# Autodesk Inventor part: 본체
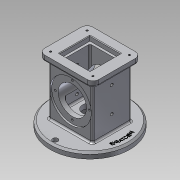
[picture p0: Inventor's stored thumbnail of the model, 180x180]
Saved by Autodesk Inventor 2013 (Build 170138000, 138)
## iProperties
Created: 2019-08
Part Number: 본체
Material: 알루미늄 6061
Document SubType Name: Modeling
Designer: default
Density: 2.71 g/cm^3
Mass: 1041.14 g
Surface Area: 787.451 cm^2
Volume: 384.186 cm^3
Author: default
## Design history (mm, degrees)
sketch "스케치1"
  geometry: C1 r 67.5 at (0, 0); 1 further point
  constraints: 1 centre point, 1 coincident
  dimensions: "d0" = 135 diameter of C1
extrude "돌출1" new body sketch "스케치1" distance "d2" = 10; taper "d3" = 0 deg
chamfer "모따기1" distance "d4" = 3; stored, may be unused: second distance "d5" = 2, angle "d6" = 45 deg
sketch "스케치2"
  geometry: L1 (-37, 33)-(37, 33); L2 (37, 33)-(37, -33); L3 (37, -33)-(-37, -33); L4 (-37, -33)-(-37, 33); L5 (-37, 33)-(37, -33); L6 (37, 33)-(-37, -33); C1 r 64.5 at (0, 0) reference
  constraints: 12 end point, 2 midpoint, 2 parallel, 1 horizontal, 1 perpendicular
  dimensions: "d7" = 74 distance of L1.start L1.end; "d9" = 66 distance of L1.end L2.end
extrude "돌출2" join sketch "스케치2" distance "d10" = 98; taper "d11" = 0 deg
sketch "스케치3"
  geometry: L1 (37, 33)-(-37, 33) reference; L2 (-37, 33)-(-37, -33) reference; L3 (-37, -33)-(37, -33) reference; L4 (37, -33)-(37, 33) reference; L5 (-46, 41)-(46, 41); L6 (46, 41)-(46, -41); L7 (46, -41)-(-46, -41); L8 (-46, -41)-(-46, 41); L9 (-46, 41)-(46, -41); L10 (46, 41)-(-46, -41); 1 further point
  constraints: 12 end point, 2 midpoint, 2 parallel, 1 horizontal, 1 perpendicular
  dimensions: "d12" = 92 distance of L5.start L5.end; "d14" = 82 distance of L5.end L6.end
extrude "돌출3" join sketch "스케치3" distance "d15" = 10; taper "d16" = 0 deg
fillet "모깎기1" dims "d17" = 10
fillet "모깎기2" dims "d18" = 3
fillet "모깎기3" dims "d19" = 3
fillet "모깎기4" dims "d20" = 3
sketch "스케치4"
  geometry: L1 (34, 36)-(-34, 36) reference; C1 r 64.5 at (0, 0) reference; 2 further points
  constraints: 2 vertical alignment, 1 midpoint
  dimensions: "d21" = 59 distance of C1.centre point (0, 59)
hole "구멍1" sketch "스케치4" at (0, 59) diameter "d22" = 9; stored, may be unused: countersink angle "d26" = 90 deg, drill point angle "d28" = 118 deg; dims "d23" = 6, "d24" = 4, "d25" = 2, "d27" = 8
sketch "스케치5"
  geometry: L1 (-26, 26)-(26, 26); L2 (26, 26)-(26, -26); L3 (26, -26)-(-26, -26); L4 (-26, -26)-(-26, 26); L5 (-26, 26)-(26, -26); L6 (26, 26)-(-26, -26); 1 further point
  constraints: 12 end point, 2 midpoint, 2 parallel, 2 perpendicular, 1 horizontal
  dimensions: "d32" = 52 distance of L1.start L1.end
extrude "돌출4" cut sketch "스케치5" distance "d34" = 8; taper "d35" = 0 deg
sketch "스케치7"
  geometry: L1 (-19, 22)-(19, 22); L2 (22, 19)-(22, -19); L3 (19, -22)-(-19, -22); L4 (-22, -19)-(-22, 19); L5 (-22, 22)-(22, -22); L6 (22, 22)-(-22, -22); A1 r 3 centre (-19, 19) between (-19, 22) and (-22, 19); A2 r 3 centre (19, 19) between (22, 19) and (19, 22); A3 r 3 centre (19, -19) between (19, -22) and (22, -19); A4 r 3 centre (-19, -19) between (-22, -19) and (-19, -22); 1 further point
  constraints: 12 end point, 8 point on circle, 8 point on line, 8 tangent, 4 centre point, 3 equal radius, 2 midpoint, 2 parallel, 2 perpendicular, 1 horizontal
  dimensions: "d36" = 44 distance of L5.start L6.start; "d38" = 3 radius of A1
extrude "돌출5" cut sketch "스케치7" distance "d39" = 74; taper "d40" = 0 deg
sketch "스케치8"
  geometry: L1 (63.5, 0)-(63.5, 10) reference; L2 (63.5, 10)-(64.5, 10) reference; L3 (64.5, 10)-(67.5, 7) reference; L4 (67.5, 7)-(67.5, 0) reference; L5 (67.5, 0)-(63.5, 0) reference; L6 (-37, 13)-(-37, 95) reference; L7 (-40, 98)-(-46, 98) reference; L8 (-46, 98)-(-46, 108) reference; L9 (-46, 108)-(-26, 108) reference; L10 (-26, 108)-(-26, 100) reference; L11 (-26, 100)-(-22, 100) reference; L12 (-22, 100)-(-22, 26) reference; L13 (-22, 26)-(22, 26) reference; L14 (22, 26)-(22, 100) reference; L15 (22, 100)-(26, 100) reference; L16 (26, 100)-(26, 108) reference; L17 (26, 108)-(46, 108) reference; L18 (46, 108)-(46, 98) reference; L19 (46, 98)-(40, 98) reference; L20 (37, 95)-(37, 13) reference; L21 (40, 10)-(54.5, 10) reference; L22 (54.5, 10)-(54.5, 0) reference; L23 (54.5, 0)-(-67.5, 0) reference; L24 (-67.5, 0)-(-67.5, 7) reference; L25 (-67.5, 7)-(-64.5, 10) reference; L26 (-64.5, 10)-(-40, 10) reference; L27 (0, 26)-(0, 0); L28 (-25, 0)-(-25, 18); L29 (-25, 18)-(0, 18); A1 r 3 centre (-40, 13) between (-40, 10) and (-37, 13) reference; A2 r 3 centre (-40, 95) between (-37, 95) and (-40, 98) reference; A3 r 3 centre (40, 95) between (40, 98) and (37, 95) reference; A4 r 3 centre (40, 13) between (37, 13) and (40, 10) reference
  constraints: 6 end point, 2 perpendicular, 2 point on line, 1 midpoint, 1 parallel
  dimensions: "d41" = 50 diameter of L28 L27; "d43" = 18 distance of L28.start L28.end
revolve "회전1" sketch "스케치8" stored, may be unused: angle "d44" = 90 deg
sketch "스케치9"
  geometry: C1 r 25 at (0, 0) reference; C2 r 12.5 at (0, 0)
  constraints: 1 centre point, 1 coincident
  dimensions: "d45" = 25 diameter of C2
extrude "돌출6" cut sketch "스케치9" stored distance "d47" = 74; taper "d48" = 0 deg
sketch "스케치10"
  geometry: A1 r 10 centre (-36, -31) between (-46, -31) and (-36, -41) reference; A2 r 10 centre (36, -31) between (36, -41) and (46, -31) reference; A3 r 10 centre (36, 31) between (46, 31) and (36, 41) reference; A4 r 10 centre (-36, 31) between (-36, 41) and (-46, 31) reference; 1 further point
hole "구멍2" sketch "스케치10" at (-36, 31), (-36, -31), (36, 31), (36, -31) diameter "d49" = 3.242; stored, may be unused: countersink angle "d53" = 90 deg, drill point angle "d55" = 118 deg; dims "d50" = 4, "d51" = 4, "d52" = 2, "d54" = 6
sketch "스케치11"
  geometry: L1 (-33.5, -13)-(101.5, -13) reference; C1 r 35 at (34, 41); 1 further point
  constraints: 1 centre point, 1 vertical alignment
  dimensions: "d56" = 70 diameter of C1; "d58" = 54 distance from line of L1 C1.centre
extrude "돌출7" cut sketch "스케치11" distance "d59" = 3; taper "d60" = 0 deg
sketch "스케치12"
  geometry: C1 r 35 at (0, 0) reference; C2 r 24 at (0, 0); 1 further point
  constraints: 1 centre point, 1 coincident
  dimensions: "d61" = 48 diameter of C2
extrude "돌출8" cut sketch "스케치12" stored distance "d63" = 3; taper "d64" = 0 deg
sketch "스케치13"
  geometry: C1 r 24 at (0, 0) reference; 2 further points
  constraints: 1 vertical alignment
  dimensions: "d65" = 29 distance of C1.centre point (0, 29)
hole "구멍3" sketch "스케치13" at (0, 29) diameter "d66" = 3.242; stored, may be unused: countersink angle "d70" = 90 deg, drill point angle "d72" = 118 deg; dims "d67" = 4, "d68" = 4, "d69" = 2, "d71" = 6
chamfer "모따기2" distance "d76" = 1; stored, may be unused: second distance "d77" = 2, angle "d78" = 45 deg
fillet "모깎기5" dims "d79" = 3
sketch "스케치14"
  geometry: L1 (13, -37.5)-(13, 97.5) reference; 3 further points
  constraints: 2 horizontal alignment
  dimensions: "d80" = 37 distance from line of L1 point (-24, 30); "d81" = 43 distance of point (-24, 30) point (-67, 30)
hole "구멍4" sketch "스케치14" at (-24, 30), (-67, 30) diameter "d82" = 4.917; stored, may be unused: countersink angle "d86" = 90 deg, drill point angle "d88" = 0 deg; dims "d83" = 100, "d84" = 4, "d85" = 2, "d87" = 6
node "작업 평면1"
sketch "스케치15"
  geometry: C1 r 59 at (0, 0); 1 further point
  constraints: 1 centre point, 1 coincident, 1 other
  dimensions: "d90" = 118 diameter of C1
feature "엠보싱1" sketch "스케치15" dims "d92" = 0.5, "d93" = 0
fillet "모깎기6" dims "d94" = 3
fillet "모깎기7" dims "d95" = 3
node "솔리드1"
pattern_circular "원형 패턴1" dims angle "d30" = 180 deg
pattern_circular "원형 패턴2" dims angle "d74" = 360 deg
mirror "대칭1"
node "절단 모서리 투영1"
other parameters: "d89" = 42.75
